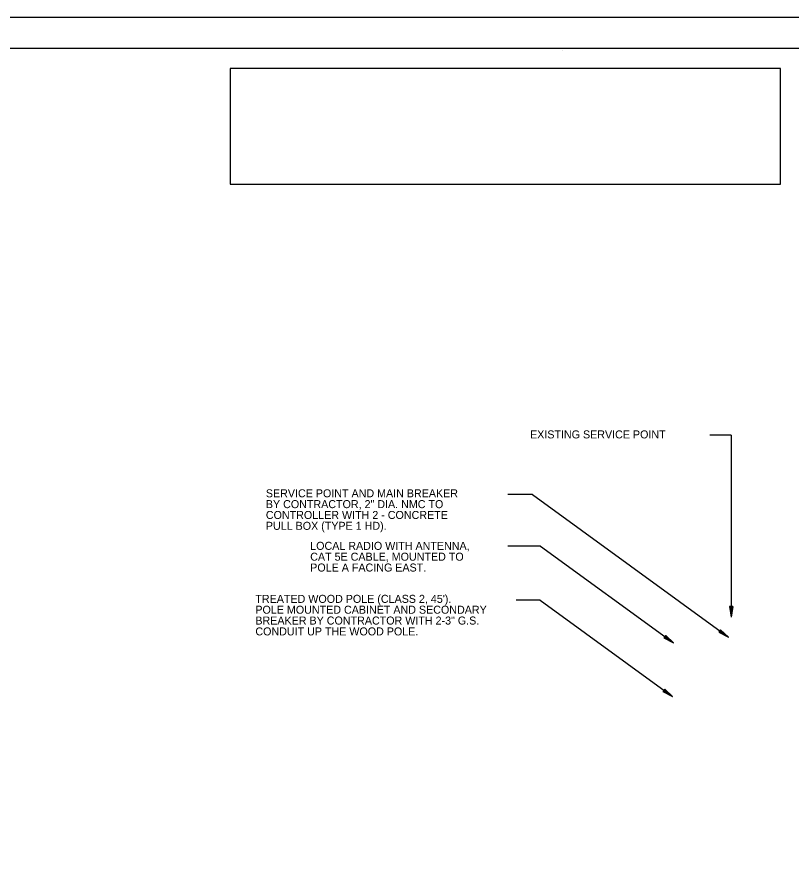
# Model space of a CAD drawing. Extents: x 662183 to 663183, y 642099 to 642739.
# Drawn here: x 662473 to 662763.4, y 642419.3 to 642739.3 of the extents above; entities that cross this region are included whole.
import ezdxf

# ---------------------------------------------------------------- set-up
doc = ezdxf.new("R2010")
doc.units = 0
for name, color, linetype in [('R_Border', 7, 'Continuous'), ('R_No Plot', 7, 'Continuous'), ('T_Drafting', 7, 'Continuous')]:
    doc.layers.add(name, color=color, linetype=linetype)

msp = doc.modelspace()

# ---------------------------------------------------------------- linework, layer by layer
at = {"layer": 'R_Border'}
for p, q in [((662219.86, 642727.62), (663168.4, 642727.62)), ((662677.42, 642726.84), (662677.42, 642726.84)), ((662677.42, 642726.84), (662677.42, 642726.84))]:
    msp.add_line(p, q, dxfattribs=at)
at = {"layer": 'R_No Plot'}
msp.add_line((662182.66, 642739.3), (663182.66, 642739.3), dxfattribs=at)
msp.add_lwpolyline([(662182.64, 642739.3), (663182.66, 642739.3), (663182.66, 642099.29), (662182.64, 642099.29)], close=True, dxfattribs=at)
at = {"layer": 'T_Drafting'}
for p, q in [((662740.61, 642582.59), (662732.58, 642582.59)), ((662740.61, 642582.59), (662740.61, 642514.4)), ((662666.14, 642560.31), (662656.91, 642560.31)), ((662666.14, 642560.31), (662739.55, 642506.86)), ((662669.16, 642541.02), (662656.91, 642541.02)), ((662669.16, 642541.02), (662718.99, 642504.72)), ((662669.04, 642520.75), (662660.1, 642520.75)), ((662669.04, 642520.75), (662718.65, 642484.62)), ((662740.01, 642518.4), (662740.61, 642514.4)), ((662741.21, 642518.4), (662740.01, 642518.4)), ((662740.11, 642518.4), (662740.61, 642515.07)), ((662740.21, 642518.4), (662740.61, 642515.75)), ((662740.31, 642518.4), (662740.61, 642516.42)), ((662740.41, 642518.4), (662740.61, 642517.1)), ((662740.51, 642518.4), (662740.61, 642517.77)), ((662741.21, 642518.4), (662740.61, 642514.4)), ((662740.8, 642518.4), (662740.61, 642517.1)), ((662741.01, 642518.4), (662740.61, 642515.75)), ((662741.11, 642518.4), (662740.61, 642515.07)), ((662740.91, 642518.4), (662740.61, 642516.42)), ((662740.7, 642518.4), (662740.61, 642517.77)), ((662736.67, 642509.7), (662735.96, 642508.73)), ((662736.08, 642508.89), (662738.45, 642507.66)), ((662736.14, 642508.97), (662737.91, 642508.05)), ((662736.2, 642509.05), (662737.37, 642508.45)), ((662736.26, 642509.14), (662736.83, 642508.84)), ((662736.37, 642509.29), (662736.83, 642508.84)), ((662736.43, 642509.37), (662737.37, 642508.45)), ((662736.49, 642509.45), (662737.91, 642508.05)), ((662736.55, 642509.53), (662738.45, 642507.66)), ((662736.61, 642509.62), (662739.01, 642507.25)), ((662736.67, 642509.7), (662739.55, 642506.86)), ((662716.11, 642507.56), (662715.41, 642506.59)), ((662715.41, 642506.59), (662718.99, 642504.72)), ((662715.47, 642506.67), (662718.45, 642505.12)), ((662715.53, 642506.76), (662717.9, 642505.52)), ((662715.58, 642506.84), (662717.36, 642505.91)), ((662715.64, 642506.92), (662716.81, 642506.31)), ((662715.7, 642507), (662716.27, 642506.71)), ((662715.82, 642507.15), (662716.27, 642506.71)), ((662715.87, 642507.23), (662716.81, 642506.31)), ((662715.94, 642507.32), (662717.36, 642505.91)), ((662715.99, 642507.4), (662717.9, 642505.52)), ((662716.05, 642507.48), (662718.45, 642505.12)), ((662716.11, 642507.56), (662718.99, 642504.72)), ((662735.96, 642508.73), (662739.55, 642506.86)), ((662736.02, 642508.81), (662739.01, 642507.25)), ((662715.77, 642487.46), (662715.06, 642486.49)), ((662715.06, 642486.49), (662718.65, 642484.62)), ((662715.12, 642486.57), (662718.11, 642485.02)), ((662715.18, 642486.66), (662717.56, 642485.42)), ((662715.24, 642486.74), (662717.02, 642485.81)), ((662715.3, 642486.82), (662716.47, 642486.21)), ((662715.36, 642486.9), (662715.93, 642486.61)), ((662715.47, 642487.05), (662715.93, 642486.61)), ((662715.53, 642487.14), (662716.47, 642486.21)), ((662715.59, 642487.22), (662717.02, 642485.81)), ((662715.65, 642487.3), (662717.56, 642485.42)), ((662715.71, 642487.38), (662718.11, 642485.02)), ((662715.77, 642487.46), (662718.65, 642484.62))]:
    msp.add_line(p, q, dxfattribs=at)
msp.add_lwpolyline([(662552.91, 642676.63), (662759.08, 642676.63), (662759.08, 642720.03), (662552.91, 642720.03)], close=True, dxfattribs=at)

# ---------------------------------------------------------------- texts
for s, p in [('EXISTING SERVICE POINT ', (662665.24, 642581.39)), ('SERVICE POINT AND MAIN BREAKER', (662566.24, 642559.32)), ('BY CONTRACTOR, 2" DIA. NMC TO', (662566.24, 642555.26)), ('CONTROLLER WITH 2 - CONCRETE', (662566.24, 642551.2)), ('PULL BOX (TYPE 1 HD).', (662566.24, 642547.13)), ('LOCAL RADIO WITH ANTENNA,', (662582.86, 642539.63)), ('CAT 5E CABLE, MOUNTED TO', (662582.86, 642535.56)), ('POLE A FACING EAST.', (662582.86, 642531.5)), ("TREATED WOOD POLE (CLASS 2, 45').", (662562.31, 642519.76)), ('POLE MOUNTED CABINET AND SECONDARY', (662562.31, 642515.69)), ('BREAKER BY CONTRACTOR WITH 2-3" G.S.', (662562.31, 642511.63)), ('CONDUIT UP THE WOOD POLE.', (662562.31, 642507.56))]:
    msp.add_text(s, height=3, dxfattribs=at).set_placement(p)

doc.saveas('drawing.dxf')
